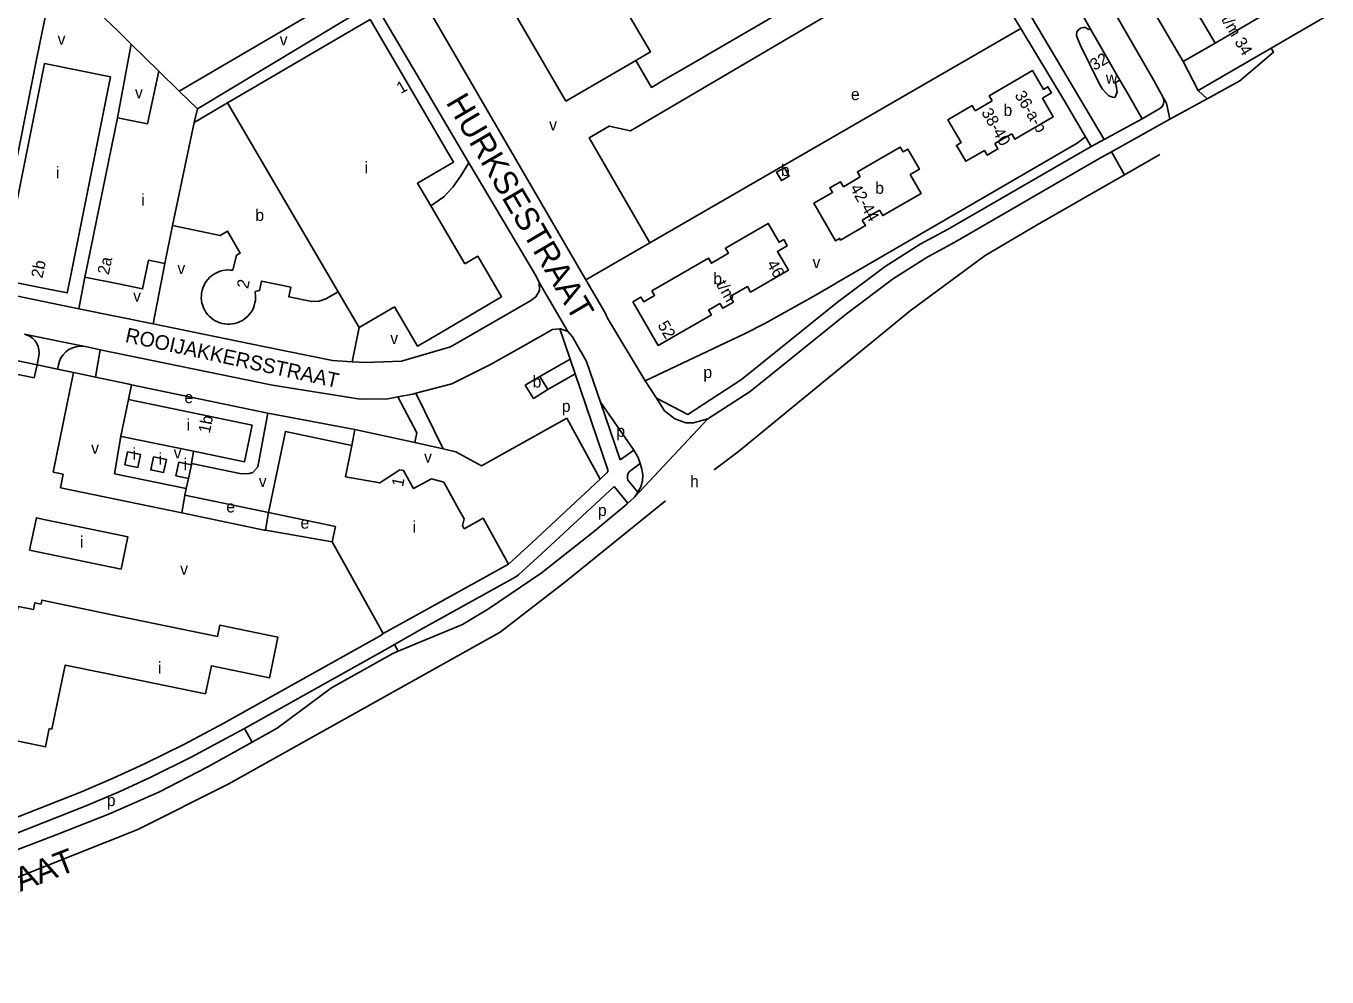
# Model space of a CAD drawing. Extents: x 157699 to 159683, y 381451 to 383293.
# Drawn here: x 158968.6 to 159410.6, y 382033.3 to 382356.5 of the extents above; entities that cross this region are included whole.
import ezdxf

# ---------------------------------------------------------------- set-up
doc = ezdxf.new("R2010")
doc.units = 0
for name, color, linetype in [('BLT_Basislijn', 7, 'Continuous'), ('BLT_Bebouwing', 7, 'Continuous'), ('BLT_Centroide', 7, 'Continuous'), ('BLT_Huisnummer', 7, 'Continuous'), ('BLT_Huisnummer_reeks', 7, 'Continuous'), ('BLT_Onderverdeling_panden', 7, 'Continuous'), ('BLT_Straatnaam', 7, 'Continuous'), ('BLT_Straatnaam_hoofdweg', 7, 'Continuous'), ('BLT_Vlakafsluiter', 7, 'Continuous')]:
    doc.layers.add(name, color=color, linetype=linetype)

msp = doc.modelspace()

# ---------------------------------------------------------------- linework, layer by layer
at = {"layer": 'BLT_Basislijn'}
for p, q in [((159285.94, 382400.36), (159334.86, 382317.96)), ((159086.9, 382364.52), (159026.81, 382328.36)), ((159103.9, 382364.71), (159158.8, 382270.22)), ((159326.45, 382362.08), (159330.13, 382355.66)), ((159361.69, 382344.41), (159350.24, 382363.95)), ((159410.57, 382359.98), (159391.6, 382348.99)), ((159306.55, 382355.63), (159180.52, 382282.77)), ((159330.13, 382355.66), (159340.22, 382338.11)), ((158999.69, 382325.34), (159004.34, 382350.32)), ((159372.57, 382350.66), (159361.69, 382344.41)), ((159391.6, 382348.99), (159366.79, 382334.62)), ((159366.79, 382334.62), (159361.69, 382344.41)), ((159340.22, 382338.11), (159343.11, 382333.08)), ((159369.92, 382331.76), (159366.79, 382334.62)), ((159343.11, 382333.08), (159347.81, 382324.9)), ((159334.86, 382317.96), (159347.81, 382324.9)), ((159337.36, 382313.75), (159357.14, 382324.87)), ((159328.58, 382318.8), (159330.4, 382315.56)), ((159330.4, 382315.56), (159334.86, 382317.96)), ((159332.84, 382311.2), (159337.36, 382313.75)), ((159341.76, 382305.9), (159353.79, 382312.86)), ((159180.52, 382282.77), (159158.8, 382270.22)), ((159015.7, 382275.77), (159011.73, 382255.34)), ((158988.57, 382271.15), (158986.47, 382260.39)), ((159243.82, 382269.13), (159236.97, 382265.18)), ((158956.46, 382266.56), (158986.47, 382260.39)), ((159011.73, 382255.34), (158986.47, 382260.39)), ((158891.33, 382258.3), (158972.31, 382241.32)), ((158971.38, 382236.96), (158900.34, 382251.44)), ((158968.06, 382251.75), (158980.78, 382249.13)), ((159081.71, 382254.08), (159079.36, 382242.37)), ((159212.63, 382251.85), (159178.96, 382235.88)), ((158980.78, 382249.13), (158988.12, 382247.65)), ((158988.12, 382247.65), (158989.75, 382247.32)), ((158989.75, 382247.32), (158993.77, 382246.48)), ((159052.36, 382234.47), (158993.77, 382246.48)), ((159137.44, 382247.68), (159126.38, 382241.42)), ((158972.96, 382244.4), (158972.31, 382241.32)), ((159153.41, 382243.33), (159143.11, 382237.41)), ((158972.31, 382241.32), (158971.38, 382236.96)), ((158972.31, 382241.32), (158979.27, 382239.86)), ((158984.71, 382238.71), (158977.83, 382204.85)), ((158979.61, 382241.41), (158979.27, 382239.86)), ((158984.71, 382238.71), (158979.27, 382239.86)), ((158987.94, 382238.03), (158984.71, 382238.71)), ((158987.94, 382238.03), (158992.21, 382237.13)), ((159146.69, 382233.41), (159155.11, 382238.33)), ((159004.37, 382234.6), (159003.38, 382229.56)), ((159050.73, 382224.91), (159004.37, 382234.6)), ((159082.07, 382229.66), (159052.36, 382234.47)), ((159145.86, 382232.92), (159146.69, 382233.41)), ((159101.02, 382231.71), (159110.27, 382212.79)), ((159080.27, 382219.39), (159050.73, 382224.91)), ((159000.8, 382217.06), (158998.63, 382204.34)), ((159079.32, 382213.96), (159080.27, 382219.39)), ((159024.85, 382207.84), (159025.42, 382211.98)), ((159110.27, 382212.79), (159100.71, 382214.98)), ((159175.05, 382212.35), (159170.4, 382209.02)), ((159024.76, 382207.42), (159024.85, 382207.84)), ((159177.24, 382207.77), (159173.58, 382205.15)), ((158977.83, 382204.85), (158981.2, 382204.18)), ((158980.27, 382199.59), (158981.2, 382204.18)), ((158998.63, 382204.34), (159022.98, 382199.28)), ((159022.98, 382199.28), (159023.8, 382202.77)), ((159021.55, 382191.05), (158980.27, 382199.59)), ((159022.55, 382197.05), (159022.98, 382199.28)), ((159173.07, 382194.32), (159168.37, 382200.05)), ((159051, 382191.21), (159022.55, 382197.05)), ((159051, 382191.21), (159049.92, 382185.13)), ((159072.6, 382181.17), (159049.92, 382185.13)), ((159094.98, 382144.05), (159093.77, 382146.27)), ((159042.78, 382117.78), (159045.4, 382113.11))]:
    msp.add_line(p, q, dxfattribs=at)
for points in [[(159351.7, 382337.93), (159296.79, 382433.33), (159275.51, 382470.3)], [(159175.76, 382344.81), (159152.01, 382330.98), (159122.37, 382381.82), (159126.95, 382397), (159140.75, 382404.94)], [(159180.52, 382282.77), (159159.85, 382318.49), (159166.7, 382322.45), (159173.96, 382320.88), (159257.22, 382369.88), (159266.66, 382367.11), (159290.9, 382381.46)], [(159290.9, 382381.46), (159306.55, 382355.63)], [(158978.31, 382375.44), (158972.33, 382346.27), (158956.46, 382266.56)], [(159086.9, 382364.52), (159100, 382342.33), (159119.07, 382310.05)], [(159306.55, 382355.63), (159321.19, 382331.46), (159328.58, 382318.8)], [(159330.13, 382355.66), (159329.56, 382355.34), (159328.56, 382356), (159327.81, 382356.01), (159326.79, 382355.78), (159325.99, 382355.1), (159325.55, 382354.5), (159325.47, 382353.3), (159325.95, 382352.02), (159326.83, 382349.9), (159333.19, 382337.01), (159334.27, 382335.05), (159335.51, 382333.69), (159336.47, 382332.81), (159337.67, 382332.33), (159338.47, 382332.25), (159338.89, 382332.93), (159339.24, 382334.18), (159339.11, 382335.48), (159338.78, 382337.29), (159340.22, 382338.11)], [(159369.92, 382331.76), (159380.98, 382337.85), (159392.4, 382347.61), (159391.6, 382348.99)], [(159354.97, 382332.25), (159351.7, 382337.93)], [(159347.81, 382324.9), (159353.83, 382328.42), (159354.51, 382329), (159355, 382329.99), (159355.18, 382330.82), (159355.18, 382331.45), (159354.97, 382332.25)], [(159354.97, 382332.25), (159356.03, 382330.23), (159357.14, 382324.87)], [(159300.51, 382302.02), (159325.73, 382316.68), (159328.58, 382318.8)], [(159182.74, 382229.98), (159193.4, 382224.51), (159211.71, 382236.39), (159244.23, 382262.69), (159260.47, 382274.79), (159272.39, 382282.37), (159281.66, 382287.37), (159330.4, 382315.56)], [(159106.07, 382295.4), (159110.58, 382298.49), (159113.63, 382301.71), (159116.34, 382305.53), (159119.07, 382310.05)], [(159119.07, 382310.05), (159141.84, 382271.52), (159142.95, 382269.3)], [(159200.27, 382223.01), (159214.65, 382232.34), (159247.29, 382258.74), (159263.31, 382270.67), (159274.93, 382278.05), (159284.1, 382283), (159332.84, 382311.2)], [(159202.39, 382205.68), (159210.65, 382211.87), (159232.08, 382229.43), (159269.01, 382259.67), (159294.42, 382278.49), (159312.16, 382288.89), (159341.76, 382305.9)], [(159300.51, 382302.02), (159244.16, 382269.33), (159243.82, 382269.13)], [(159142.95, 382269.3), (159143, 382266.59), (159141.81, 382264.51), (159139.8, 382263.02), (159112.84, 382247.51), (159100, 382243.7), (159096.17, 382242.61), (159083.91, 382242.1), (159079.36, 382242.37)], [(159158.8, 382270.22), (159165.33, 382259.08), (159166.17, 382257.17), (159178.96, 382235.88)], [(159236.97, 382265.18), (159219.64, 382255.41), (159212.63, 382251.85)], [(159079.36, 382242.37), (159072.69, 382242.84), (159049.27, 382247.63), (159011.73, 382255.34)], [(158968.06, 382251.75), (158969.02, 382251.44), (158969.97, 382250.97), (158970.86, 382250.31), (158971.64, 382249.5), (158972.27, 382248.56), (158972.72, 382247.53), (158972.98, 382246.46), (158973.05, 382245.4), (158972.96, 382244.4)], [(159149.92, 382253.54), (159147.4, 382253.33), (159137.44, 382247.68)], [(159152.67, 382252.65), (159150.11, 382253.55), (159149.92, 382253.54)], [(159153.41, 382243.33), (159149.92, 382253.54)], [(159157.28, 382245.56), (159156.9, 382246.25), (159154.22, 382250.83), (159152.67, 382252.65)], [(158988.12, 382247.65), (158986.81, 382247.68), (158985.57, 382247.52), (158984.33, 382247.13), (158983.15, 382246.54), (158982.08, 382245.74), (158981.16, 382244.78), (158980.44, 382243.7), (158979.92, 382242.56), (158979.61, 382241.41)], [(158993.77, 382246.48), (158992.21, 382237.13)], [(159155.11, 382238.33), (159153.41, 382243.33)], [(159157.28, 382245.56), (159158.97, 382242.51), (159163.71, 382228.62)], [(159126.38, 382241.42), (159113.22, 382234.95), (159101.02, 382231.71)], [(159163.61, 382202.46), (159165.91, 382204.6), (159166.26, 382205.08), (159166.25, 382205.68), (159155.11, 382238.33)], [(158992.21, 382237.13), (159003.57, 382234.77), (159004.37, 382234.6)], [(159178.96, 382235.88), (159182.74, 382229.98)], [(159094.9, 382230.46), (159091.46, 382229.8), (159082.07, 382229.66)], [(159101.02, 382231.71), (159100, 382231.44), (159094.9, 382230.46)], [(159100.71, 382214.98), (159101.33, 382218.27), (159094.9, 382230.46)], [(159170.4, 382209.02), (159163.71, 382228.62)], [(159175.05, 382212.35), (159174.8, 382212.75), (159163.71, 382228.62)], [(159182.74, 382229.98), (159185.48, 382225.71), (159189, 382222.97), (159192.73, 382221.59), (159195.34, 382221.61), (159200.18, 382222.98)], [(159050.73, 382224.91), (159047.33, 382206.73), (159045.58, 382204.82), (159044.4, 382204.39), (159041.76, 382204.27), (159024.85, 382207.84)], [(159110.27, 382212.79), (159114.65, 382211.84), (159123.3, 382207.01), (159152.26, 382223.28)], [(159152.26, 382223.28), (159163.61, 382202.46)], [(159200.18, 382222.98), (159200.27, 382223.01)], [(159080.27, 382219.39), (159100.71, 382214.98)], [(159177.24, 382207.77), (159176.59, 382209.82), (159175.05, 382212.35)], [(159176.45, 382198.08), (159177.46, 382199.9), (159178.02, 382201.93), (159178.15, 382203.84), (159177.85, 382205.87), (159177.24, 382207.77)], [(159163.61, 382202.46), (159140.37, 382180.85), (159132.52, 382173.66)], [(159176.45, 382198.08), (159173.07, 382202.21), (159172.9, 382202.99), (159172.91, 382203.75), (159173.14, 382204.49), (159173.58, 382205.15)], [(159168.37, 382200.05), (159143.76, 382177.18), (159135.89, 382169.97)], [(159175.39, 382196.5), (159176.45, 382198.08)], [(158870.97, 382033.32), (158878.88, 382035.05), (158896.8, 382040.83), (158932.11, 382053.92), (159006.54, 382083.5), (159037.22, 382098.8), (159129.65, 382150.55), (159151.52, 382167.42), (159185.85, 382195.18)], [(159021.55, 382191.05), (159022.28, 382195.61), (159022.55, 382197.05)], [(159094.98, 382144.05), (159116.88, 382153.15), (159125.7, 382158.46), (159143.54, 382170.56), (159161.22, 382184.46), (159172.75, 382194.04), (159173.07, 382194.32)], [(159173.07, 382194.32), (159175.21, 382196.24)], [(159175.21, 382196.24), (159175.39, 382196.5)], [(159021.55, 382191.05), (159049.46, 382185.21), (159049.92, 382185.13)], [(159135.89, 382169.97), (159134.94, 382169.29), (159102.43, 382151.25), (159093.77, 382146.27)], [(159089.91, 382150.02), (159088.85, 382149.22), (159035.79, 382119.61), (159022.43, 382112.48), (159008.87, 382105.74), (158998.17, 382100.87), (158987.38, 382096.23), (158934.38, 382075.37)], [(159091.59, 382145.02), (159042.78, 382117.78)], [(159093.77, 382146.27), (159091.59, 382145.02)], [(159045.4, 382113.11), (159053.89, 382117.86), (159072.39, 382131.63), (159093.21, 382143.31), (159094.98, 382144.05)], [(159042.78, 382117.78), (159038.18, 382115.22), (159024.72, 382108.03), (159011.02, 382101.22), (159000.2, 382096.29), (158989.28, 382091.61), (158936.12, 382070.68)], [(158937.86, 382066.01), (158978.78, 382081.64), (158996.94, 382088.82), (159013.88, 382096.22), (159030.16, 382104.6), (159045.4, 382113.11)]]:
    msp.add_lwpolyline(points, dxfattribs=at)
at = {"layer": 'BLT_Bebouwing'}
for p, q in [((159199.93, 382346.62), (159254.08, 382378.19)), ((159004.34, 382350.32), (159013.72, 382341.15)), ((159198.7, 382345.91), (159199.93, 382346.62)), ((159025.73, 382323.72), (159037.04, 382330.34)), ((159117.62, 382275.68), (159106.07, 382295.4)), ((159018.36, 382288.73), (159015.7, 382275.77)), ((159081.71, 382254.08), (159074.65, 382266.14)), ((159093.75, 382261.07), (159081.71, 382254.08)), ((159143.11, 382237.41), (159138.21, 382234.42)), ((159145.86, 382232.92), (159143.11, 382237.41)), ((159138.21, 382234.42), (159140.95, 382229.92)), ((159000.8, 382217.06), (159003.38, 382229.56)), ((159140.95, 382229.92), (159145.86, 382232.92)), ((159001.03, 382217.01), (159000.8, 382217.06)), ((159025.42, 382211.98), (159001.03, 382217.01)), ((159079.32, 382213.96), (159077.08, 382203.25)), ((159023.8, 382202.77), (159024.76, 382207.42)), ((159073.71, 382186.46), (159051, 382191.21)), ((159072.6, 382181.17), (159073.71, 382186.46))]:
    msp.add_line(p, q, dxfattribs=at)
for points in [[(159379.22, 382376.15), (159363.14, 382366.71), (159372.57, 382350.66)], [(159372.57, 382350.66), (159388.64, 382360.1), (159379.22, 382376.15)], [(159074.38, 382373.05), (159077.52, 382367.68), (159073.21, 382365.16), (159020.64, 382334.39)], [(159161.13, 382369.99), (159166.04, 382361.53), (159171.04, 382364.31), (159180.7, 382347.7), (159175.76, 382344.81)], [(158995.24, 382359.2), (159000.07, 382354.49), (159004.34, 382350.32)], [(159037.04, 382330.34), (159081.15, 382356.17), (159085.47, 382358.7), (159100, 382333.88), (159113.82, 382310.27), (159101.57, 382303.09), (159106.07, 382295.4)], [(158983.58, 382270.68), (158997.24, 382339.24), (158974.85, 382343.71), (158961.19, 382275.18), (158960.22, 382270.28), (158982.61, 382265.78), (158983.58, 382270.68)], [(159175.76, 382344.81), (159181.1, 382335.65), (159185.42, 382338.17), (159198.7, 382345.91)], [(159013.72, 382341.15), (159009.85, 382323.26), (158999.69, 382325.34)], [(159303.45, 382319.89), (159304.51, 382318.05), (159317.57, 382325.61), (159313.89, 382331.97), (159317, 382333.76), (159315.79, 382335.86), (159314.24, 382334.97), (159310.56, 382341.33), (159295.77, 382332.77), (159296.77, 382331.03)], [(159020.64, 382334.39), (159026.81, 382328.36)], [(159296.77, 382331.03), (159291.04, 382327.72)], [(159026.81, 382328.36), (159025.73, 382323.72)], [(159291.04, 382327.72), (159290.04, 382329.45), (159281.76, 382324.66), (159286.27, 382316.86), (159284.69, 382315.94), (159287.83, 382310.53), (159294.21, 382314.22), (159295.13, 382312.62), (159298.75, 382314.71), (159297.68, 382316.55)], [(158988.57, 382271.15), (158989.6, 382276.06), (158999.69, 382325.34)], [(159297.68, 382316.55), (159303.45, 382319.89)], [(159258.57, 382293.9), (159259.63, 382292.06), (159272.68, 382299.61), (159268.99, 382305.99), (159272.12, 382307.8), (159268.13, 382314.7), (159266.53, 382313.78), (159265.6, 382315.38), (159251.02, 382306.93), (159252.02, 382305.21)], [(159252.02, 382305.21), (159246.27, 382301.87)], [(159246.27, 382301.87), (159245.26, 382303.6), (159241.66, 382301.52), (159242.58, 382299.93), (159236.23, 382296.25), (159243.58, 382283.54), (159244.96, 382284.34), (159245.3, 382283.76), (159253.77, 382288.67), (159252.71, 382290.51)], [(159252.71, 382290.51), (159258.57, 382293.9)], [(159018.36, 382288.73), (159034.57, 382285.35), (159037.03, 382286.78), (159041.35, 382279.36), (159040.05, 382278.6), (159038.84, 382273.49)], [(159117.62, 382275.68), (159122.05, 382278.28), (159130.16, 382264.44), (159105.52, 382250), (159101.59, 382247.7), (159100, 382250.42), (159093.75, 382261.07)], [(159015.7, 382275.77), (159010.15, 382276.91), (159008.15, 382267.13), (159000, 382268.83), (158988.57, 382271.15)], [(159038.84, 382273.49), (159037.98, 382273.58), (159037.12, 382273.6), (159036.27, 382273.54), (159035.42, 382273.4), (159034.59, 382273.18), (159033.78, 382272.88), (159033.01, 382272.52), (159032.27, 382272.08), (159031.57, 382271.57), (159030.93, 382271), (159030.34, 382270.38), (159029.82, 382269.7), (159029.35, 382268.97), (159028.96, 382268.21), (159028.64, 382267.41), (159028.4, 382266.59), (159028.23, 382265.75), (159028.14, 382264.89), (159028.13, 382264.03), (159028.21, 382263.18), (159028.36, 382262.33), (159028.59, 382261.5), (159028.89, 382260.7), (159029.27, 382259.93), (159029.72, 382259.2), (159030.23, 382258.51), (159030.81, 382257.87), (159031.44, 382257.29), (159032.13, 382256.77), (159032.86, 382256.32), (159033.62, 382255.94), (159034.43, 382255.63), (159035.25, 382255.39), (159036.1, 382255.24), (159036.95, 382255.16), (159037.81, 382255.16), (159038.67, 382255.24), (159039.51, 382255.41), (159040.34, 382255.65), (159041.13, 382255.96), (159041.9, 382256.35), (159042.63, 382256.8), (159043.31, 382257.33), (159043.94, 382257.91), (159044.51, 382258.55), (159045.02, 382259.24), (159045.47, 382259.98), (159045.84, 382260.75), (159046.14, 382261.56), (159046.36, 382262.39), (159046.51, 382263.23), (159046.58, 382264.09), (159046.56, 382264.95), (159046.47, 382265.8), (159046.39, 382266.27)], [(159046.39, 382266.27), (159047.85, 382266.59), (159048.6, 382269.83), (159058.49, 382267.76), (159057.86, 382264.5), (159065.66, 382262.87), (159068.14, 382262.94), (159070.47, 382263.81), (159074.65, 382266.14)], [(159003.38, 382229.56), (159045.38, 382220.89), (159042.8, 382208.39), (159026.04, 382211.85), (159025.42, 382211.98)], [(159051, 382191.21), (159055.69, 382213.8), (159056.71, 382218.7), (159079.32, 382213.96)], [(159003.08, 382211.84), (159007.47, 382210.93), (159006.56, 382206.49), (159002.17, 382207.4), (159003.08, 382211.84)], [(159011.86, 382210.08), (159016.25, 382209.18), (159015.33, 382204.72), (159010.94, 382205.62), (159011.86, 382210.08)], [(159023.8, 382202.77), (159019.49, 382203.65), (159020.44, 382208.3)], [(159020.44, 382208.3), (159024.76, 382207.42)], [(159077.08, 382203.25), (159088.74, 382201.25), (159095.63, 382205.67), (159096.84, 382205.41), (159100, 382199.72), (159100.24, 382199.29), (159106.3, 382202.66), (159110.5, 382201.46), (159115.76, 382191.99), (159117.44, 382188.98), (159116.83, 382186.79), (159117.46, 382185.64), (159123.88, 382189.21), (159132.52, 382173.66)], [(158969.81, 382178.39), (159000.89, 382171.96), (159003.16, 382182.93), (158998.31, 382183.93), (158974.63, 382188.84), (158972.09, 382189.37), (158969.81, 382178.39)], [(159089.91, 382150.02), (159087.48, 382154.39), (159072.6, 382181.17)], [(159132.52, 382173.66), (159100, 382155.62), (159089.91, 382150.02)], [(159033.59, 382149.04), (159000, 382155.99), (158973.95, 382161.39), (158973.68, 382160.05), (158971.6, 382160.48), (158971.11, 382158.16), (158965.85, 382159.25), (158959, 382126.18), (158958.03, 382121.53), (158958.97, 382121.34), (158957.68, 382115.13), (158975.15, 382111.51), (158976.45, 382117.75), (158977.37, 382117.56), (158981.89, 382139.33), (158995.39, 382136.53), (159029.58, 382129.54)], [(159029.58, 382129.54), (159031.55, 382139.07), (159051.28, 382134.98), (159052.29, 382139.88), (159054.14, 382148.79), (159034.39, 382152.88), (159033.59, 382149.04)]]:
    msp.add_lwpolyline(points, dxfattribs=at)
for points in [[(159223.56, 382306.8), (159226.21, 382308.34), (159227.86, 382305.48), (159225.21, 382303.95)], [(159174.77, 382262.8), (159183.39, 382247.92), (159201.42, 382258.36), (159200.5, 382259.96), (159204.34, 382262.18), (159205.26, 382260.59), (159208.89, 382262.69), (159207.82, 382264.53), (159213.67, 382267.92), (159214.74, 382266.08), (159227.57, 382273.51), (159223.88, 382279.9), (159227.21, 382281.82), (159225.99, 382283.92), (159224.44, 382283.03), (159220.75, 382289.39), (159206.22, 382280.98), (159207.22, 382279.26), (159201.41, 382275.9), (159200.41, 382277.61), (159181.2, 382266.49), (159182.11, 382264.92), (159178.42, 382262.79), (159177.49, 382264.38)]]:
    msp.add_lwpolyline(points, close=True, dxfattribs=at)
at = {"layer": 'BLT_Onderverdeling_panden'}
for p, q in [((159020.64, 382334.39), (159013.72, 382341.15)), ((159074.65, 382266.14), (159037.04, 382330.34)), ((159018.36, 382288.73), (159025.73, 382323.72))]:
    msp.add_line(p, q, dxfattribs=at)
at = {"layer": 'BLT_Vlakafsluiter'}
for p, q in [((159357.14, 382324.87), (159369.92, 382331.76)), ((159341.76, 382305.9), (159337.36, 382313.75)), ((159142.95, 382269.3), (159152.67, 382252.65)), ((159175.21, 382196.24), (159200.27, 382223.01)), ((159175.39, 382196.5), (159200.18, 382222.98))]:
    msp.add_line(p, q, dxfattribs=at)

# ---------------------------------------------------------------- texts
at = {"layer": 'BLT_Centroide'}
for s, p in [('v', (158979.29, 382350.12)), ('v', (159054.76, 382349.93)), ('w', (159335.46, 382336.91)), ('v', (159005.6, 382331.95)), ('e', (159248.84, 382331.32)), ('b', (159300.67, 382325.94)), ('v', (159146.31, 382321.02)), ('i', (158978.73, 382304.75)), ('i', (159083.59, 382306.39)), ('b', (159225.02, 382305.52)), ('b', (159257.09, 382299.47)), ('i', (159007.69, 382295.47)), ('b', (159046.5, 382290.25)), ('v', (159235.8, 382274.28)), ('v', (159020, 382272.24)), ('b', (159202.07, 382268.66)), ('v', (159004.97, 382262.84)), ('v', (159092.33, 382248.43)), ('b', (159140.69, 382233.66)), ('p', (159198.72, 382236.87)), ('e', (159022.41, 382228.33)), ('p', (159150.61, 382225.36)), ('i', (159023.09, 382218.97)), ('p', (159169.12, 382216.88)), ('v', (158990.7, 382211.13)), ('i', (159004.81, 382209.16)), ('i', (159013.59, 382207.39)), ('v', (159018.74, 382209.54)), ('v', (159103.8, 382208.12)), ('i', (159022.12, 382205.55)), ('v', (159047.66, 382199.88)), ('h', (159194.19, 382199.76)), ('e', (159036.61, 382191.19)), ('e', (159061.82, 382185.69)), ('p', (159162.87, 382189.97)), ('i', (159099.92, 382184.34)), ('i', (158986.9, 382179.17)), ('v', (159020.94, 382170)), ('i', (159013.41, 382136.44)), ('p', (158996.01, 382091.39))]:
    msp.add_text(s, height=4, dxfattribs=at).set_placement(p)
at = {"layer": 'BLT_Huisnummer'}
for s, rotation, p in [('32', 30.0738, (159331.52, 382341.22)), ('1', 30.3572, (159095.92, 382333.33)), ('2a', 77.7814, (158996.66, 382271.75)), ('2b', 78.431, (158974.14, 382270.61)), ('2', 77.7814, (159044, 382267.02)), ('1b', 78.3423, (159030.98, 382217.89)), ('1', 78.6638, (159096.62, 382199.73))]:
    msp.add_text(s, height=4, rotation=rotation, dxfattribs=at).set_placement(p)
at = {"layer": 'BLT_Huisnummer_reeks'}
for s, rotation, p in [('30 t/m 34', 300.4264, (159370.74, 382365.28)), ('36-a-b', 301.1765, (159304.31, 382333.04)), ('38-40', 300.0634, (159293.01, 382327.17)), ('42-44', 300.073, (159248.37, 382301.44)), ('46', 300.0714, (159220.08, 382275.63)), ('t/m', 300.0771, (159202.9, 382268.7)), ('52', 300.0725, (159183.02, 382254.9))]:
    msp.add_text(s, height=4, rotation=rotation, dxfattribs=at).set_placement(p)
at = {"layer": 'BLT_Straatnaam'}
msp.add_text('ROOIJAKKERSSTRAAT', height=5, rotation=347.7165, dxfattribs=at).set_placement((159002.01, 382249.18))
at = {"layer": 'BLT_Straatnaam_hoofdweg'}
for s, rotation, p in [('HURKSESTRAAT', 300.4072, (159111.05, 382330.55)), ('BEEMDSTRAAT', 21.3388, (158911.24, 382040.59))]:
    msp.add_text(s, height=8, rotation=rotation, dxfattribs=at).set_placement(p)

doc.saveas('drawing.dxf')
